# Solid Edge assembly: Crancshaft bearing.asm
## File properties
Author: KULL
Template: Iso Metric Assembly.asm
Last saved by: KULL
Revision: 9
Application: Solid Edge
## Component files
Crankshaft bearings.par
ballring.par
laagri kuulid.par
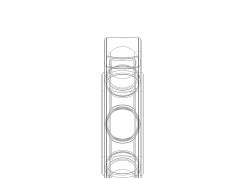
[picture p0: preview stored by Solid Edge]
